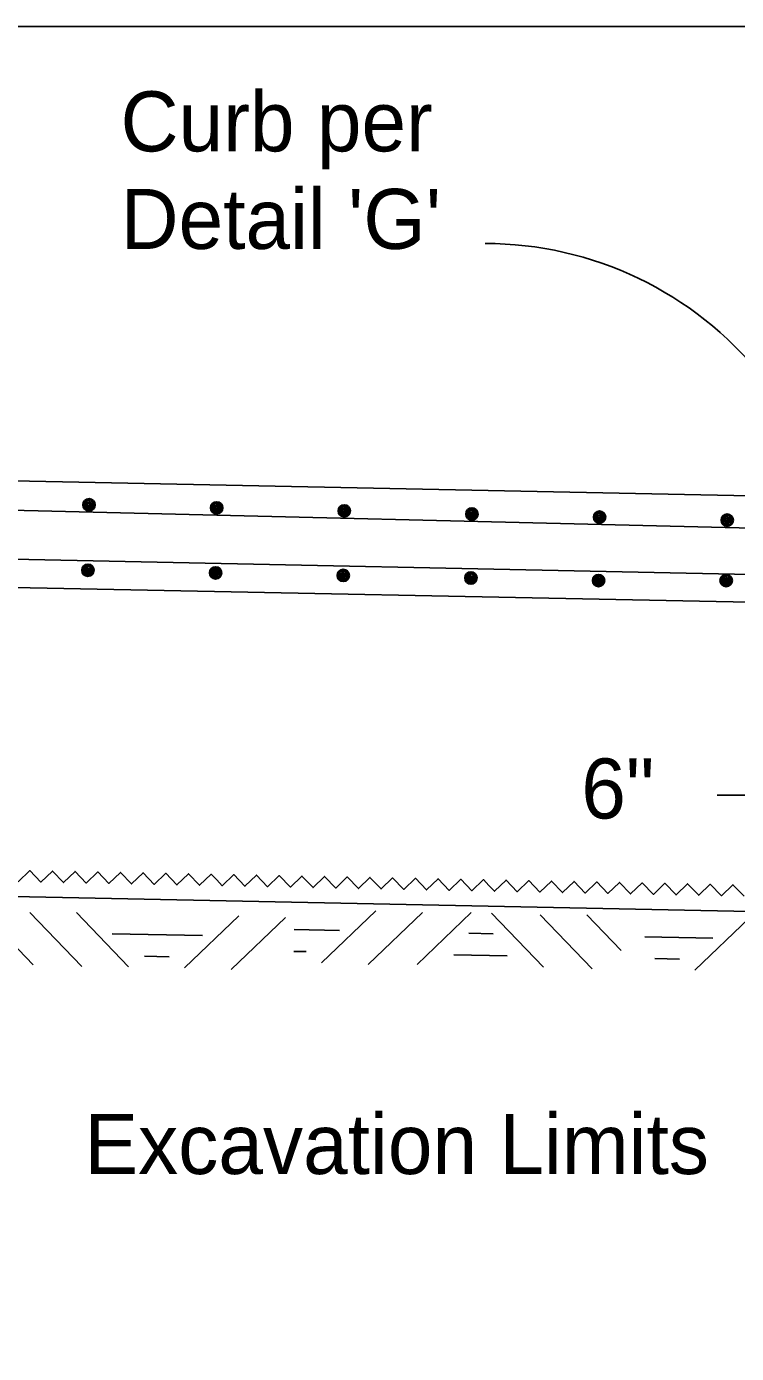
# Model space of a CAD drawing. Extents: x 10130 to 81668, y 5440 to 21644.
# Drawn here: x 17977.5 to 18166.8, y 9590.3 to 9944 of the extents above; entities that cross this region are included whole.
import ezdxf

# ---------------------------------------------------------------- set-up
doc = ezdxf.new("R2010")
doc.units = 0
for name, color, linetype in [('dsnNonPlotable', 7, 'Continuous'), ('dsnStdBlockModified', 7, 'Continuous'), ('dsnStdBlockNotModified', 7, 'Continuous'), ('dsnStdBorder', 7, 'Continuous'), ('SheetBorder', 7, 'Continuous')]:
    doc.layers.add(name, color=color, linetype=linetype)

msp = doc.modelspace()

# ---------------------------------------------------------------- linework, layer by layer
at = {"layer": 'dsnNonPlotable'}
msp.add_line((18198.14, 9739.18), (18161.6, 9739.18), dxfattribs=at)
at = {"layer": 'dsnStdBlockModified'}
msp.add_line((18198.1, 9797.36), (17466.58, 9812.52), dxfattribs=at)
at = {"layer": 'dsnStdBlockNotModified'}
msp.add_arc((18099.79, 9791.67), 94.53, 38.8378, 90, dxfattribs=at)
at = {"layer": 'dsnStdBorder'}
for p, q in [((18176.88, 9818.81), (17466.62, 9833.07)), ((17466.62, 9833.07), (18176.88, 9818.81)), ((17466.59, 9827.31), (18198.18, 9809.65)), ((17466.05, 9804.71), (18215.16, 9789.67)), ((17467.19, 9804.69), (18215.16, 9789.67)), ((17466.62, 9722.28), (18283.21, 9705.89)), ((17965.41, 9708.36), (17979.26, 9693.93)), ((17978.41, 9707.87), (17992.26, 9693.45)), ((17990.86, 9707.85), (18004.72, 9693.42)), ((18034.08, 9706.98), (18019.65, 9693.12)), ((18046.52, 9706.5), (18032.1, 9692.65)), ((18070.61, 9708.34), (18056.19, 9694.48)), ((18083.06, 9707.86), (18068.63, 9694.01)), ((18096.07, 9707.83), (18081.64, 9693.97)), ((18101.48, 9707.72), (18115.33, 9693.3)), ((18114.48, 9707.23), (18128.33, 9692.81)), ((18126.93, 9707.21), (18136.03, 9697.73)), ((18170.15, 9706.34), (18155.72, 9692.48))]:
    msp.add_line(p, q, dxfattribs=at)
for points in [[(17992.64, 9816.48), (17992.92, 9817.03), (17993.22, 9817.88), (17994.11, 9818.01), (17994.88, 9817.86), (17995.57, 9817.28), (17995.46, 9816.45), (17995.3, 9815.59), (17994.59, 9815.2), (17993.85, 9815.15), (17992.92, 9815.71), (17992.87, 9816.35), (17993.12, 9817.21), (17993.71, 9817.9), (17994.53, 9817.84), (17995.17, 9817.26), (17995.21, 9816.47), (17995.01, 9815.61), (17994.51, 9815.5), (17993.91, 9815.35), (17993.22, 9815.79), (17993.26, 9816.42), (17993.41, 9817.14), (17993.84, 9817.64), (17994.55, 9817.35), (17994.95, 9816.78), (17994.94, 9816.05), (17994.54, 9815.89), (17994.09, 9815.67), (17993.53, 9816.06), (17993.42, 9816.6), (17993.7, 9817.07), (17994.24, 9817.08), (17994.61, 9816.81), (17994.72, 9816.31), (17994.5, 9816.08), (17994.2, 9815.96), (17993.78, 9816.23), (17993.71, 9816.58), (17993.93, 9816.91), (17994.22, 9816.83), (17994.39, 9816.58), (17994.37, 9816.24), (17994.13, 9816.25), (17994, 9816.56)], [(18026.67, 9815.66), (18026.95, 9816.21), (18027.25, 9817.06), (18028.14, 9817.19), (18028.91, 9817.04), (18029.6, 9816.45), (18029.49, 9815.63), (18029.33, 9814.77), (18028.62, 9814.38), (18027.88, 9814.34), (18026.95, 9814.89), (18026.9, 9815.53), (18027.15, 9816.39), (18027.74, 9817.08), (18028.56, 9817.01), (18029.21, 9816.43), (18029.24, 9815.65), (18029.04, 9814.79), (18028.54, 9814.67), (18027.94, 9814.52), (18027.25, 9814.97), (18027.29, 9815.6), (18027.44, 9816.31), (18027.87, 9816.82), (18028.58, 9816.53), (18028.98, 9815.96), (18028.97, 9815.23), (18028.57, 9815.06), (18028.12, 9814.85), (18027.56, 9815.23), (18027.45, 9815.78), (18027.73, 9816.25), (18028.27, 9816.26), (18028.64, 9815.98), (18028.75, 9815.49), (18028.53, 9815.26), (18028.23, 9815.14), (18027.81, 9815.41), (18027.74, 9815.76), (18027.96, 9816.08), (18028.25, 9816.02), (18028.42, 9815.76), (18028.4, 9815.42), (18028.16, 9815.43), (18028.04, 9815.74)], [(18060.7, 9814.84), (18060.97, 9815.38), (18061.28, 9816.24), (18062.17, 9816.37), (18062.94, 9816.22), (18063.63, 9815.63), (18063.52, 9814.81), (18063.36, 9813.94), (18062.65, 9813.56), (18061.91, 9813.51), (18060.98, 9814.07), (18060.93, 9814.71), (18061.18, 9815.57), (18061.77, 9816.25), (18062.59, 9816.2), (18063.24, 9815.61), (18063.27, 9814.83), (18063.07, 9813.97), (18062.57, 9813.86), (18061.97, 9813.7), (18061.28, 9814.15), (18061.32, 9814.77), (18061.47, 9815.5), (18061.9, 9816), (18062.61, 9815.7), (18063.01, 9815.14), (18063, 9814.41), (18062.6, 9814.24), (18062.15, 9814.03), (18061.59, 9814.42), (18061.48, 9814.96), (18061.76, 9815.43), (18062.3, 9815.44), (18062.67, 9815.17), (18062.78, 9814.67), (18062.56, 9814.44), (18062.26, 9814.31), (18061.84, 9814.59), (18061.77, 9814.94), (18061.99, 9815.26), (18062.28, 9815.19), (18062.45, 9814.94), (18062.43, 9814.59), (18062.19, 9814.61), (18062.06, 9814.92)], [(18094.73, 9814.02), (18095, 9814.57), (18095.31, 9815.42), (18096.2, 9815.55), (18096.97, 9815.4), (18097.66, 9814.81), (18097.55, 9813.99), (18097.39, 9813.12), (18096.68, 9812.74), (18095.94, 9812.69), (18095.01, 9813.25), (18094.96, 9813.89), (18095.21, 9814.75), (18095.8, 9815.43), (18096.62, 9815.37), (18097.26, 9814.79), (18097.3, 9814.01), (18097.1, 9813.14), (18096.6, 9813.03), (18096, 9812.88), (18095.31, 9813.32), (18095.35, 9813.95), (18095.5, 9814.67), (18095.92, 9815.18), (18096.64, 9814.88), (18097.04, 9814.32), (18097.03, 9813.59), (18096.63, 9813.42), (18096.17, 9813.21), (18095.62, 9813.59), (18095.51, 9814.14), (18095.79, 9814.61), (18096.33, 9814.61), (18096.7, 9814.34), (18096.8, 9813.85), (18096.59, 9813.62), (18096.29, 9813.49), (18095.87, 9813.77), (18095.8, 9814.12), (18096.02, 9814.44), (18096.31, 9814.38), (18096.48, 9814.12), (18096.46, 9813.78), (18096.21, 9813.79), (18096.09, 9814.09)], [(18128.76, 9813.2), (18129.03, 9813.74), (18129.34, 9814.6), (18130.23, 9814.73), (18131, 9814.58), (18131.69, 9813.99), (18131.58, 9813.17), (18131.41, 9812.3), (18130.71, 9811.92), (18129.97, 9811.87), (18129.04, 9812.43), (18128.98, 9813.06), (18129.24, 9813.92), (18129.83, 9814.61), (18130.65, 9814.55), (18131.29, 9813.97), (18131.33, 9813.18), (18131.13, 9812.32), (18130.63, 9812.21), (18130.03, 9812.06), (18129.33, 9812.5), (18129.38, 9813.13), (18129.53, 9813.85), (18129.95, 9814.36), (18130.67, 9814.06), (18131.06, 9813.5), (18131.06, 9812.76), (18130.65, 9812.6), (18130.2, 9812.39), (18129.65, 9812.77), (18129.54, 9813.32), (18129.82, 9813.78), (18130.36, 9813.8), (18130.72, 9813.53), (18130.84, 9813.03), (18130.62, 9812.8), (18130.32, 9812.67), (18129.9, 9812.95), (18129.83, 9813.3), (18130.05, 9813.62), (18130.34, 9813.55), (18130.51, 9813.3), (18130.49, 9812.95), (18130.24, 9812.97), (18130.12, 9813.28)], [(18162.79, 9812.38), (18163.06, 9812.93), (18163.37, 9813.78), (18164.26, 9813.91), (18165.03, 9813.75), (18165.72, 9813.17), (18165.61, 9812.34), (18165.44, 9811.48), (18164.74, 9811.09), (18164, 9811.05), (18163.06, 9811.6), (18163.01, 9812.24), (18163.27, 9813.1), (18163.86, 9813.79), (18164.68, 9813.73), (18165.32, 9813.15), (18165.36, 9812.36), (18165.15, 9811.5), (18164.66, 9811.39), (18164.06, 9811.24), (18163.36, 9811.68), (18163.41, 9812.31), (18163.56, 9813.03), (18163.99, 9813.53), (18164.7, 9813.24), (18165.09, 9812.68), (18165.09, 9811.95), (18164.69, 9811.78), (18164.23, 9811.57), (18163.68, 9811.95), (18163.57, 9812.5), (18163.85, 9812.97), (18164.39, 9812.97), (18164.75, 9812.7), (18164.87, 9812.2), (18164.65, 9811.98), (18164.35, 9811.85), (18163.93, 9812.12), (18163.86, 9812.47), (18164.08, 9812.8), (18164.37, 9812.73), (18164.54, 9812.47), (18164.52, 9812.13), (18164.27, 9812.15), (18164.15, 9812.45)], [(17995.4, 9798.95), (17995.15, 9799.51), (17994.88, 9800.38), (17994, 9800.55), (17993.23, 9800.42), (17992.51, 9799.87), (17992.58, 9799.04), (17992.71, 9798.17), (17993.4, 9797.76), (17994.13, 9797.68), (17995.09, 9798.19), (17995.17, 9798.82), (17994.95, 9799.7), (17994.39, 9800.41), (17993.57, 9800.39), (17992.9, 9799.83), (17992.83, 9799.05), (17993, 9798.18), (17993.49, 9798.05), (17994.08, 9797.87), (17994.79, 9798.28), (17994.78, 9798.91), (17994.66, 9799.64), (17994.26, 9800.16), (17993.53, 9799.9), (17993.11, 9799.35), (17993.08, 9798.62), (17993.48, 9798.44), (17993.92, 9798.2), (17994.5, 9798.56), (17994.63, 9799.1), (17994.37, 9799.58), (17993.83, 9799.62), (17993.45, 9799.36), (17993.32, 9798.87), (17993.52, 9798.63), (17993.82, 9798.5), (17994.25, 9798.75), (17994.33, 9799.09), (17994.13, 9799.43), (17993.84, 9799.37), (17993.65, 9799.12), (17993.66, 9798.78), (17993.91, 9798.79), (17994.04, 9799.09)], [(18029.43, 9798.26), (18029.18, 9798.82), (18028.92, 9799.69), (18028.04, 9799.86), (18027.26, 9799.74), (18026.55, 9799.19), (18026.62, 9798.36), (18026.74, 9797.49), (18027.43, 9797.07), (18028.17, 9796.99), (18029.12, 9797.51), (18029.2, 9798.14), (18028.98, 9799.01), (18028.42, 9799.73), (18027.6, 9799.71), (18026.94, 9799.15), (18026.86, 9798.37), (18027.03, 9797.49), (18027.52, 9797.36), (18028.11, 9797.19), (18028.83, 9797.6), (18028.81, 9798.23), (18028.69, 9798.96), (18028.29, 9799.48), (18027.56, 9799.21), (18027.14, 9798.67), (18027.12, 9797.94), (18027.51, 9797.76), (18027.95, 9797.52), (18028.53, 9797.88), (18028.66, 9798.42), (18028.4, 9798.9), (18027.86, 9798.93), (18027.48, 9798.68), (18027.35, 9798.19), (18027.55, 9797.95), (18027.85, 9797.81), (18028.28, 9798.07), (18028.37, 9798.41), (18028.16, 9798.75), (18027.87, 9798.69), (18027.68, 9798.44), (18027.7, 9798.1), (18027.94, 9798.11), (18028.08, 9798.41)], [(18063.46, 9797.58), (18063.22, 9798.14), (18062.95, 9799.01), (18062.07, 9799.18), (18061.29, 9799.06), (18060.58, 9798.5), (18060.65, 9797.67), (18060.78, 9796.81), (18061.47, 9796.39), (18062.2, 9796.31), (18063.16, 9796.82), (18063.23, 9797.46), (18063.02, 9798.33), (18062.46, 9799.04), (18061.64, 9799.02), (18060.97, 9798.47), (18060.9, 9797.68), (18061.06, 9796.81), (18061.55, 9796.68), (18062.14, 9796.5), (18062.86, 9796.91), (18062.84, 9797.55), (18062.73, 9798.27), (18062.32, 9798.79), (18061.6, 9798.53), (18061.18, 9797.98), (18061.15, 9797.26), (18061.55, 9797.07), (18061.99, 9796.84), (18062.56, 9797.2), (18062.69, 9797.74), (18062.43, 9798.22), (18061.9, 9798.25), (18061.52, 9797.99), (18061.39, 9797.5), (18061.59, 9797.27), (18061.88, 9797.13), (18062.31, 9797.38), (18062.4, 9797.73), (18062.2, 9798.06), (18061.9, 9798.01), (18061.72, 9797.76), (18061.73, 9797.42), (18061.97, 9797.42), (18062.11, 9797.72)], [(18097.5, 9796.9), (18097.25, 9797.46), (18096.98, 9798.33), (18096.1, 9798.5), (18095.32, 9798.38), (18094.61, 9797.82), (18094.68, 9796.99), (18094.8, 9796.12), (18095.5, 9795.7), (18096.23, 9795.63), (18097.19, 9796.14), (18097.27, 9796.78), (18097.05, 9797.65), (18096.49, 9798.36), (18095.67, 9798.34), (18095, 9797.78), (18094.93, 9797), (18095.1, 9796.13), (18095.59, 9796), (18096.18, 9795.82), (18096.89, 9796.23), (18096.88, 9796.86), (18096.76, 9797.59), (18096.35, 9798.11), (18095.63, 9797.85), (18095.21, 9797.3), (18095.18, 9796.57), (18095.58, 9796.39), (18096.02, 9796.16), (18096.59, 9796.52), (18096.72, 9797.05), (18096.47, 9797.53), (18095.93, 9797.57), (18095.55, 9797.31), (18095.42, 9796.82), (18095.62, 9796.58), (18095.91, 9796.45), (18096.35, 9796.7), (18096.43, 9797.05), (18096.23, 9797.38), (18095.94, 9797.32), (18095.75, 9797.08), (18095.76, 9796.73), (18096, 9796.74), (18096.14, 9797.04)], [(18131.53, 9796.22), (18131.28, 9796.78), (18131.01, 9797.64), (18130.13, 9797.81), (18129.36, 9797.69), (18128.64, 9797.14), (18128.71, 9796.31), (18128.84, 9795.44), (18129.53, 9795.02), (18130.26, 9794.94), (18131.22, 9795.46), (18131.3, 9796.09), (18131.08, 9796.96), (18130.53, 9797.68), (18129.7, 9797.65), (18129.04, 9797.1), (18128.96, 9796.32), (18129.13, 9795.45), (18129.62, 9795.31), (18130.21, 9795.14), (18130.93, 9795.55), (18130.91, 9796.18), (18130.79, 9796.9), (18130.39, 9797.43), (18129.66, 9797.17), (18129.24, 9796.62), (18129.21, 9795.89), (18129.61, 9795.7), (18130.05, 9795.47), (18130.63, 9795.83), (18130.76, 9796.37), (18130.5, 9796.85), (18129.96, 9796.88), (18129.58, 9796.63), (18129.45, 9796.14), (18129.65, 9795.9), (18129.95, 9795.76), (18130.38, 9796.02), (18130.47, 9796.36), (18130.26, 9796.7), (18129.97, 9796.64), (18129.78, 9796.39), (18129.79, 9796.05), (18130.04, 9796.06), (18130.17, 9796.35)], [(18162.52, 9796.22), (18162.77, 9796.78), (18163.04, 9797.64), (18163.92, 9797.81), (18164.7, 9797.69), (18165.41, 9797.14), (18165.34, 9796.31), (18165.21, 9795.44), (18164.52, 9795.02), (18163.79, 9794.94), (18162.83, 9795.46), (18162.75, 9796.09), (18162.97, 9796.96), (18163.53, 9797.68), (18164.35, 9797.65), (18165.02, 9797.1), (18165.09, 9796.32), (18164.92, 9795.45), (18164.43, 9795.31), (18163.84, 9795.14), (18163.12, 9795.55), (18163.14, 9796.18), (18163.26, 9796.9), (18163.67, 9797.43), (18164.39, 9797.17), (18164.81, 9796.62), (18164.84, 9795.89), (18164.44, 9795.7), (18164, 9795.47), (18163.43, 9795.83), (18163.29, 9796.37), (18163.55, 9796.85), (18164.09, 9796.88), (18164.47, 9796.63), (18164.6, 9796.14), (18164.4, 9795.9), (18164.11, 9795.76), (18163.67, 9796.02), (18163.59, 9796.36), (18163.79, 9796.7), (18164.08, 9796.64), (18164.27, 9796.39), (18164.26, 9796.05), (18164.02, 9796.06), (18163.88, 9796.35)], [(17975.25, 9716.08), (17978.34, 9719.05), (17981.3, 9715.96), (17984.39, 9718.92), (17987.35, 9715.84), (17990.43, 9718.8), (17993.4, 9715.72), (17996.48, 9718.68), (17999.45, 9715.6), (18002.53, 9718.56), (18005.5, 9715.48), (18008.58, 9718.44), (18011.54, 9715.35), (18014.63, 9718.31), (18017.59, 9715.23), (18020.68, 9718.19), (18023.64, 9715.11), (18026.73, 9718.08), (18028.21, 9716.53)], [(18028.21, 9716.53), (18029.69, 9714.99), (18032.78, 9717.95), (18035.74, 9714.87), (18038.83, 9717.83), (18041.79, 9714.74), (18044.87, 9717.71), (18047.84, 9714.62), (18050.92, 9717.59), (18053.89, 9714.5), (18056.97, 9717.47), (18059.94, 9714.38), (18063.02, 9717.34), (18065.98, 9714.26), (18069.07, 9717.22), (18072.03, 9714.14), (18075.12, 9717.1), (18078.08, 9714.02), (18081.17, 9716.98), (18084.13, 9713.9), (18087.22, 9716.86), (18090.18, 9713.77), (18093.26, 9716.74), (18096.23, 9713.65), (18099.31, 9716.62), (18100.79, 9715.07)], [(18100.79, 9715.07), (18102.28, 9713.53), (18105.36, 9716.5), (18108.33, 9713.41), (18111.41, 9716.37), (18114.37, 9713.29), (18117.46, 9716.25), (18120.42, 9713.17), (18123.51, 9716.13), (18126.47, 9713.05), (18129.56, 9716.01), (18132.52, 9712.93), (18135.61, 9715.89), (18138.57, 9712.8), (18141.65, 9715.77), (18144.62, 9712.68), (18147.7, 9715.65), (18150.67, 9712.56), (18153.75, 9715.52), (18156.71, 9712.44), (18159.8, 9715.4), (18162.76, 9712.32), (18165.85, 9715.28), (18168.81, 9712.2)], [(18000.33, 9702.18), (18024.39, 9701.7)], [(18048.9, 9703.3), (18060.92, 9703.06)], [(18095.4, 9702.34), (18101.93, 9702.21)], [(18142.39, 9701.42), (18160.46, 9701.06)], [(18008.98, 9696.21), (18015.51, 9696.08)], [(18048.78, 9697.5), (18052.04, 9697.43)], [(18091.45, 9696.56), (18105.64, 9696.28)], [(18145.05, 9695.57), (18151.58, 9695.44)]]:
    msp.add_lwpolyline(points, dxfattribs=at)
for centre in [(17994.16, 9816.54), (18028.19, 9815.72), (18062.22, 9814.9), (18096.25, 9814.08), (18130.28, 9813.26), (18164.31, 9812.44), (17993.88, 9799.08), (18027.92, 9798.39), (18061.95, 9797.71), (18095.98, 9797.03), (18130.01, 9796.34), (18164.04, 9796.34)]:
    msp.add_circle(centre, 1.65, dxfattribs=at)
at = {"layer": 'SheetBorder'}
msp.add_lwpolyline([(17332.52, 9944.02), (20467.53, 9944.02), (20467.53, 7924.02), (17332.52, 7924.02)], close=True, dxfattribs=at)

# ---------------------------------------------------------------- texts
at = {"layer": 'dsnNonPlotable'}
msp.add_text('6"', height=16, dxfattribs=at).set_placement((18125.41, 9732.92))
at = {"layer": 'dsnStdBlockNotModified'}
for s, p in [('Curb per ', (18002.58, 9910.74)), ("Detail 'G'", (18002.58, 9884.74)), ('Excavation Limits', (17992.97, 9638.15))]:
    msp.add_text(s, height=16, dxfattribs=at).set_placement(p)

doc.saveas('drawing.dxf')
